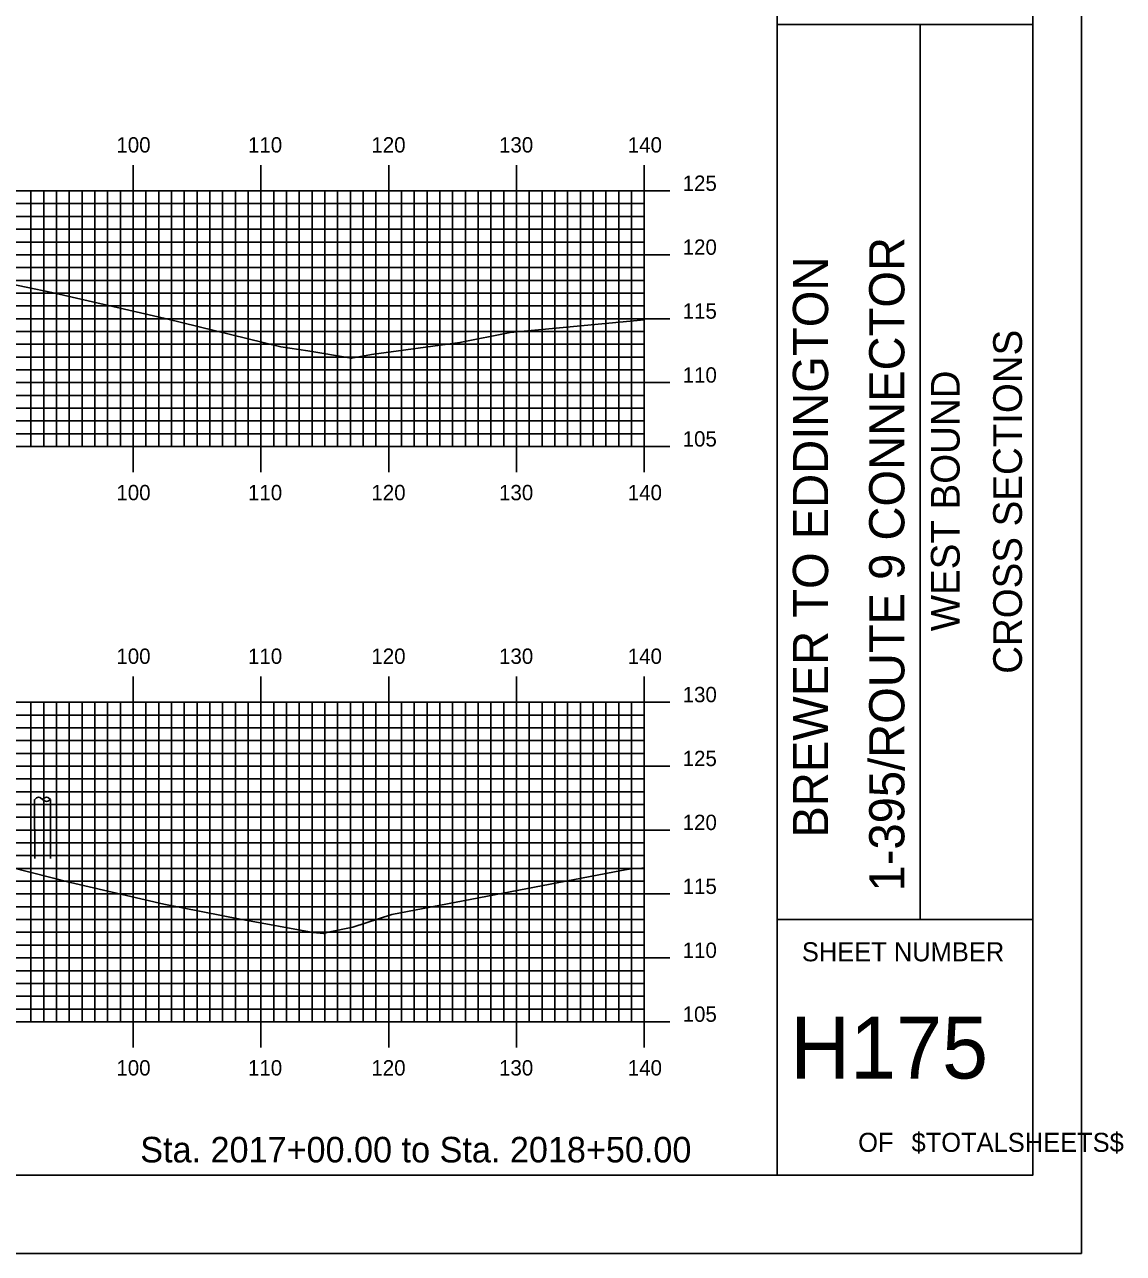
# Model space of a CAD drawing. Extents: x 855074 to 855418, y 366605 to 366825.
# Drawn here: x 855331.6 to 855417.6, y 366604.9 to 366701.1 of the extents above; entities that cross this region are included whole.
import ezdxf

# ---------------------------------------------------------------- set-up
doc = ezdxf.new("R2010")
doc.units = 0
for name, color, linetype in [('BORDER', 7, 'Continuous'), ('H_V ANNOTATION', 7, 'Continuous'), ('MAJOR', 7, 'Continuous'), ('MINOR', 7, 'Continuous'), ('PLOT BOUNDARY', 7, 'Continuous'), ('S_Roadway_Centerline', 7, 'Continuous'), ('S_Utilities_Pole_StreetLight', 7, 'Continuous')]:
    doc.layers.add(name, color=color, linetype=linetype)

msp = doc.modelspace()

# ---------------------------------------------------------------- linework, layer by layer
at = {"layer": 'BORDER'}
for p, q in [((855390.469, 366611.055), (855390.469, 366821.055)), ((855390.469, 366701.061), (855410.469, 366701.061)), ((855401.651, 366631.061), (855401.651, 366701.061)), ((855390.469, 366631.061), (855410.469, 366631.061))]:
    msp.add_line(p, q, dxfattribs=at)
msp.add_lwpolyline([(855090.469, 366611.055), (855410.469, 366611.055), (855410.469, 366821.055), (855090.469, 366821.055)], close=True, dxfattribs=at)
at = {"layer": 'MAJOR'}
for p, q in [((855340.069, 366690.059), (855340.069, 366688.055)), ((855350.069, 366690.059), (855350.069, 366688.055)), ((855360.069, 366690.059), (855360.069, 366688.055)), ((855370.069, 366690.059), (855370.069, 366688.055)), ((855380.069, 366690.059), (855380.069, 366688.055)), ((855100.069, 366688.055), (855380.069, 366688.055)), ((855100.069, 366688.055), (855380.069, 366688.055)), ((855340.069, 366668.055), (855340.069, 366688.055)), ((855350.069, 366668.055), (855350.069, 366688.055)), ((855360.069, 366668.055), (855360.069, 366688.055)), ((855370.069, 366668.055), (855370.069, 366688.055)), ((855382.073, 366688.055), (855378.065, 366688.055)), ((855380.069, 366668.055), (855380.069, 366688.055)), ((855380.069, 366668.055), (855380.069, 366688.055)), ((855100.069, 366683.055), (855380.069, 366683.055)), ((855382.073, 366683.055), (855378.065, 366683.055)), ((855100.069, 366678.055), (855380.069, 366678.055)), ((855382.073, 366678.055), (855378.065, 366678.055)), ((855100.069, 366673.055), (855380.069, 366673.055)), ((855382.073, 366673.055), (855378.065, 366673.055)), ((855100.069, 366668.055), (855380.069, 366668.055)), ((855100.069, 366668.055), (855380.069, 366668.055)), ((855340.069, 366666.051), (855340.069, 366668.055)), ((855350.069, 366666.051), (855350.069, 366668.055)), ((855360.069, 366666.051), (855360.069, 366668.055)), ((855370.069, 366666.051), (855370.069, 366668.055)), ((855382.073, 366668.055), (855378.065, 366668.055)), ((855380.069, 366666.051), (855380.069, 366668.055)), ((855340.069, 366650.059), (855340.069, 366648.055)), ((855350.069, 366650.059), (855350.069, 366648.055)), ((855360.069, 366650.059), (855360.069, 366648.055)), ((855370.069, 366650.059), (855370.069, 366648.055)), ((855380.069, 366650.059), (855380.069, 366648.055)), ((855100.069, 366648.055), (855380.069, 366648.055)), ((855100.069, 366648.055), (855380.069, 366648.055)), ((855340.069, 366623.055), (855340.069, 366648.055)), ((855350.069, 366623.055), (855350.069, 366648.055)), ((855360.069, 366623.055), (855360.069, 366648.055)), ((855370.069, 366623.055), (855370.069, 366648.055)), ((855382.073, 366648.055), (855378.065, 366648.055)), ((855380.069, 366623.055), (855380.069, 366648.055)), ((855380.069, 366623.055), (855380.069, 366648.055)), ((855100.069, 366643.055), (855380.069, 366643.055)), ((855382.073, 366643.055), (855378.065, 366643.055)), ((855100.069, 366638.055), (855380.069, 366638.055)), ((855382.073, 366638.055), (855378.065, 366638.055)), ((855100.069, 366633.055), (855380.069, 366633.055)), ((855382.073, 366633.055), (855378.065, 366633.055)), ((855100.069, 366628.055), (855380.069, 366628.055)), ((855382.073, 366628.055), (855378.065, 366628.055)), ((855100.069, 366623.055), (855380.069, 366623.055)), ((855100.069, 366623.055), (855380.069, 366623.055)), ((855340.069, 366621.051), (855340.069, 366623.055)), ((855350.069, 366621.051), (855350.069, 366623.055)), ((855360.069, 366621.051), (855360.069, 366623.055)), ((855370.069, 366621.051), (855370.069, 366623.055)), ((855382.073, 366623.055), (855378.065, 366623.055)), ((855380.069, 366621.051), (855380.069, 366623.055))]:
    msp.add_line(p, q, dxfattribs=at)
at = {"layer": 'MINOR'}
for p, q in [((855332.069, 366668.055), (855332.069, 366688.055)), ((855333.069, 366668.055), (855333.069, 366688.055)), ((855334.069, 366668.055), (855334.069, 366688.055)), ((855335.069, 366668.055), (855335.069, 366688.055)), ((855336.069, 366668.055), (855336.069, 366688.055)), ((855337.069, 366668.055), (855337.069, 366688.055)), ((855338.069, 366668.055), (855338.069, 366688.055)), ((855339.069, 366668.055), (855339.069, 366688.055)), ((855341.069, 366668.055), (855341.069, 366688.055)), ((855342.069, 366668.055), (855342.069, 366688.055)), ((855343.069, 366668.055), (855343.069, 366688.055)), ((855344.069, 366668.055), (855344.069, 366688.055)), ((855345.069, 366668.055), (855345.069, 366688.055)), ((855346.069, 366668.055), (855346.069, 366688.055)), ((855347.069, 366668.055), (855347.069, 366688.055)), ((855348.069, 366668.055), (855348.069, 366688.055)), ((855349.069, 366668.055), (855349.069, 366688.055)), ((855351.069, 366668.055), (855351.069, 366688.055)), ((855352.069, 366668.055), (855352.069, 366688.055)), ((855353.069, 366668.055), (855353.069, 366688.055)), ((855354.069, 366668.055), (855354.069, 366688.055)), ((855355.069, 366668.055), (855355.069, 366688.055)), ((855356.069, 366668.055), (855356.069, 366688.055)), ((855357.069, 366668.055), (855357.069, 366688.055)), ((855358.069, 366668.055), (855358.069, 366688.055)), ((855359.069, 366668.055), (855359.069, 366688.055)), ((855361.069, 366668.055), (855361.069, 366688.055)), ((855362.069, 366668.055), (855362.069, 366688.055)), ((855363.069, 366668.055), (855363.069, 366688.055)), ((855364.069, 366668.055), (855364.069, 366688.055)), ((855365.069, 366668.055), (855365.069, 366688.055)), ((855366.069, 366668.055), (855366.069, 366688.055)), ((855367.069, 366668.055), (855367.069, 366688.055)), ((855368.069, 366668.055), (855368.069, 366688.055)), ((855369.069, 366668.055), (855369.069, 366688.055)), ((855371.069, 366668.055), (855371.069, 366688.055)), ((855372.069, 366668.055), (855372.069, 366688.055)), ((855373.069, 366668.055), (855373.069, 366688.055)), ((855374.069, 366668.055), (855374.069, 366688.055)), ((855375.069, 366668.055), (855375.069, 366688.055)), ((855376.069, 366668.055), (855376.069, 366688.055)), ((855377.069, 366668.055), (855377.069, 366688.055)), ((855378.069, 366668.055), (855378.069, 366688.055)), ((855379.069, 366668.055), (855379.069, 366688.055)), ((855100.069, 366687.055), (855380.069, 366687.055)), ((855380.069, 366687.055), (855378.065, 366687.055)), ((855100.069, 366686.055), (855380.069, 366686.055)), ((855380.069, 366686.055), (855378.065, 366686.055)), ((855100.069, 366685.055), (855380.069, 366685.055)), ((855380.069, 366685.055), (855378.065, 366685.055)), ((855100.069, 366684.055), (855380.069, 366684.055)), ((855380.069, 366684.055), (855378.065, 366684.055)), ((855100.069, 366682.055), (855380.069, 366682.055)), ((855380.069, 366682.055), (855378.065, 366682.055)), ((855100.069, 366681.055), (855380.069, 366681.055)), ((855380.069, 366681.055), (855378.065, 366681.055)), ((855100.069, 366680.055), (855380.069, 366680.055)), ((855380.069, 366680.055), (855378.065, 366680.055)), ((855100.069, 366679.055), (855380.069, 366679.055)), ((855380.069, 366679.055), (855378.065, 366679.055)), ((855100.069, 366677.055), (855380.069, 366677.055)), ((855380.069, 366677.055), (855378.065, 366677.055)), ((855100.069, 366676.055), (855380.069, 366676.055)), ((855380.069, 366676.055), (855378.065, 366676.055)), ((855100.069, 366675.055), (855380.069, 366675.055)), ((855380.069, 366675.055), (855378.065, 366675.055)), ((855100.069, 366674.055), (855380.069, 366674.055)), ((855380.069, 366674.055), (855378.065, 366674.055)), ((855100.069, 366672.055), (855380.069, 366672.055)), ((855380.069, 366672.055), (855378.065, 366672.055)), ((855100.069, 366671.055), (855380.069, 366671.055)), ((855380.069, 366671.055), (855378.065, 366671.055)), ((855100.069, 366670.055), (855380.069, 366670.055)), ((855380.069, 366670.055), (855378.065, 366670.055)), ((855100.069, 366669.055), (855380.069, 366669.055)), ((855380.069, 366669.055), (855378.065, 366669.055)), ((855332.069, 366623.055), (855332.069, 366648.055)), ((855333.069, 366623.055), (855333.069, 366648.055)), ((855334.069, 366623.055), (855334.069, 366648.055)), ((855335.069, 366623.055), (855335.069, 366648.055)), ((855336.069, 366623.055), (855336.069, 366648.055)), ((855337.069, 366623.055), (855337.069, 366648.055)), ((855338.069, 366623.055), (855338.069, 366648.055)), ((855339.069, 366623.055), (855339.069, 366648.055)), ((855341.069, 366623.055), (855341.069, 366648.055)), ((855342.069, 366623.055), (855342.069, 366648.055)), ((855343.069, 366623.055), (855343.069, 366648.055)), ((855344.069, 366623.055), (855344.069, 366648.055)), ((855345.069, 366623.055), (855345.069, 366648.055)), ((855346.069, 366623.055), (855346.069, 366648.055)), ((855347.069, 366623.055), (855347.069, 366648.055)), ((855348.069, 366623.055), (855348.069, 366648.055)), ((855349.069, 366623.055), (855349.069, 366648.055)), ((855351.069, 366623.055), (855351.069, 366648.055)), ((855352.069, 366623.055), (855352.069, 366648.055)), ((855353.069, 366623.055), (855353.069, 366648.055)), ((855354.069, 366623.055), (855354.069, 366648.055)), ((855355.069, 366623.055), (855355.069, 366648.055)), ((855356.069, 366623.055), (855356.069, 366648.055)), ((855357.069, 366623.055), (855357.069, 366648.055)), ((855358.069, 366623.055), (855358.069, 366648.055)), ((855359.069, 366623.055), (855359.069, 366648.055)), ((855361.069, 366623.055), (855361.069, 366648.055)), ((855362.069, 366623.055), (855362.069, 366648.055)), ((855363.069, 366623.055), (855363.069, 366648.055)), ((855364.069, 366623.055), (855364.069, 366648.055)), ((855365.069, 366623.055), (855365.069, 366648.055)), ((855366.069, 366623.055), (855366.069, 366648.055)), ((855367.069, 366623.055), (855367.069, 366648.055)), ((855368.069, 366623.055), (855368.069, 366648.055)), ((855369.069, 366623.055), (855369.069, 366648.055)), ((855371.069, 366623.055), (855371.069, 366648.055)), ((855372.069, 366623.055), (855372.069, 366648.055)), ((855373.069, 366623.055), (855373.069, 366648.055)), ((855374.069, 366623.055), (855374.069, 366648.055)), ((855375.069, 366623.055), (855375.069, 366648.055)), ((855376.069, 366623.055), (855376.069, 366648.055)), ((855377.069, 366623.055), (855377.069, 366648.055)), ((855378.069, 366623.055), (855378.069, 366648.055)), ((855379.069, 366623.055), (855379.069, 366648.055)), ((855100.069, 366647.055), (855380.069, 366647.055)), ((855380.069, 366647.055), (855378.065, 366647.055)), ((855100.069, 366646.055), (855380.069, 366646.055)), ((855380.069, 366646.055), (855378.065, 366646.055)), ((855100.069, 366645.055), (855380.069, 366645.055)), ((855380.069, 366645.055), (855378.065, 366645.055)), ((855100.069, 366644.055), (855380.069, 366644.055)), ((855380.069, 366644.055), (855378.065, 366644.055)), ((855100.069, 366642.055), (855380.069, 366642.055)), ((855380.069, 366642.055), (855378.065, 366642.055)), ((855100.069, 366641.055), (855380.069, 366641.055)), ((855380.069, 366641.055), (855378.065, 366641.055)), ((855100.069, 366640.055), (855380.069, 366640.055)), ((855380.069, 366640.055), (855378.065, 366640.055)), ((855100.069, 366639.055), (855380.069, 366639.055)), ((855380.069, 366639.055), (855378.065, 366639.055)), ((855100.069, 366637.055), (855380.069, 366637.055)), ((855380.069, 366637.055), (855378.065, 366637.055)), ((855100.069, 366636.055), (855380.069, 366636.055)), ((855380.069, 366636.055), (855378.065, 366636.055)), ((855100.069, 366635.055), (855380.069, 366635.055)), ((855380.069, 366635.055), (855378.065, 366635.055)), ((855100.069, 366634.055), (855380.069, 366634.055)), ((855380.069, 366634.055), (855378.065, 366634.055)), ((855100.069, 366632.055), (855380.069, 366632.055)), ((855380.069, 366632.055), (855378.065, 366632.055)), ((855100.069, 366631.055), (855380.069, 366631.055)), ((855380.069, 366631.055), (855378.065, 366631.055)), ((855100.069, 366630.055), (855380.069, 366630.055)), ((855380.069, 366630.055), (855378.065, 366630.055)), ((855100.069, 366629.055), (855380.069, 366629.055)), ((855380.069, 366629.055), (855378.065, 366629.055)), ((855100.069, 366627.055), (855380.069, 366627.055)), ((855380.069, 366627.055), (855378.065, 366627.055)), ((855100.069, 366626.055), (855380.069, 366626.055)), ((855380.069, 366626.055), (855378.065, 366626.055)), ((855100.069, 366625.055), (855380.069, 366625.055)), ((855380.069, 366625.055), (855378.065, 366625.055)), ((855100.069, 366624.055), (855380.069, 366624.055)), ((855380.069, 366624.055), (855378.065, 366624.055))]:
    msp.add_line(p, q, dxfattribs=at)
at = {"layer": 'PLOT BOUNDARY'}
msp.add_lwpolyline([(855074.283, 366604.937), (855414.283, 366604.937), (855414.283, 366824.937), (855074.283, 366824.937)], close=True, dxfattribs=at)
at = {"layer": 'S_Roadway_Centerline'}
for points in [[(855329.673, 366680.937), (855333.694, 366680.1), (855342.574, 366678.071), (855351.62, 366675.859), (855353.731, 366675.552), (855357.163, 366674.958), (855358.708, 366675.252), (855365.637, 366676.188), (855369.564, 366676.988), (855380.069, 366677.975)], [(855324.149, 366636.747), (855335.174, 366633.949), (855342.46, 366632.26), (855348.432, 366631.079), (855354.148, 366630.052), (855354.969, 366629.967), (855355.319, 366630.07), (855357.265, 366630.462), (855360.314, 366631.441), (855378.289, 366634.903), (855379.169, 366635.06), (855379.888, 366635.082), (855380.069, 366635.074)]]:
    msp.add_lwpolyline(points, dxfattribs=at)
at = {"layer": 'S_Utilities_Pole_StreetLight'}
for p, q in [((855332.36, 366635.837), (855332.357, 366640.457)), ((855332.36, 366640.457), (855332.516, 366640.567)), ((855332.828, 366640.567), (855332.985, 366640.457)), ((855333.141, 366640.567), (855332.985, 366640.457)), ((855332.985, 366640.457), (855333.141, 366640.346)), ((855333.61, 366640.457), (855333.454, 366640.567)), ((855333.454, 366640.346), (855333.61, 366640.457)), ((855333.61, 366635.837), (855333.607, 366640.457))]:
    msp.add_line(p, q, dxfattribs=at)
for centre, start, end in [((855332.672, 366640.346), 90, 125.26439), ((855332.672, 366640.346), 54.73561, 90), ((855333.297, 366640.346), 90, 125.26439), ((855333.297, 366640.567), 234.73561, 270), ((855333.297, 366640.346), 54.73561, 90), ((855333.297, 366640.567), 270, 305.26439)]:
    msp.add_arc(centre, 0.271, start, end, dxfattribs=at)

# ---------------------------------------------------------------- texts
at = {"layer": 'BORDER'}
for s, height, p in [('1-395/ROUTE 9 CONNECTOR', 2.75575, (855400.424, 366633.255)), ('BREWER TO EDDINGTON', 2.75575, (855394.453, 366637.464)), ('CROSS SECTIONS', 2.25, (855409.623, 366650.277)), ('WEST BOUND', 2.25, (855404.748, 366653.608))]:
    msp.add_text(s, height=height, rotation=90, dxfattribs=at).set_placement(p)
for s, height, p in [('SHEET NUMBER', 1.49054, (855392.4, 366627.788)), ('H175', 4.8388, (855391.5, 366618.62)), ('OF', 1.4905, (855396.803, 366612.881)), ('$TOTALSHEETS$', 1.49054, (855400.982, 366612.881))]:
    msp.add_text(s, height=height, dxfattribs=at).set_placement(p)
at = {"layer": 'H_V ANNOTATION'}
for s, height, p in [('100', 1.2, (855338.753, 366691.055)), ('110', 1.2, (855349.053, 366691.055)), ('120', 1.2, (855358.71, 366691.055)), ('130', 1.2, (855368.699, 366691.055)), ('140', 1.2, (855378.774, 366691.055)), ('125', 1.2, (855383.069, 366688.055)), ('120', 1.2, (855383.069, 366683.055)), ('115', 1.2, (855383.069, 366678.055)), ('110', 1.2, (855383.069, 366673.055)), ('105', 1.2, (855383.069, 366668.055)), ('100', 1.2, (855338.753, 366663.855)), ('110', 1.2, (855349.053, 366663.855)), ('120', 1.2, (855358.71, 366663.855)), ('130', 1.2, (855368.699, 366663.855)), ('140', 1.2, (855378.774, 366663.855)), ('100', 1.2, (855338.753, 366651.055)), ('110', 1.2, (855349.053, 366651.055)), ('120', 1.2, (855358.71, 366651.055)), ('130', 1.2, (855368.699, 366651.055)), ('140', 1.2, (855378.774, 366651.055)), ('130', 1.2, (855383.069, 366648.055)), ('125', 1.2, (855383.069, 366643.055)), ('120', 1.2, (855383.069, 366638.055)), ('115', 1.2, (855383.069, 366633.055)), ('110', 1.2, (855383.069, 366628.055)), ('105', 1.2, (855383.069, 366623.055)), ('100', 1.2, (855338.753, 366618.855)), ('110', 1.2, (855349.053, 366618.855)), ('120', 1.2, (855358.71, 366618.855)), ('130', 1.2, (855368.699, 366618.855)), ('140', 1.2, (855378.774, 366618.855)), ('Sta. 2017+00.00 to Sta. 2018+50.00', 2.0004, (855340.622, 366612.055))]:
    msp.add_text(s, height=height, dxfattribs=at).set_placement(p)

doc.saveas('drawing.dxf')
